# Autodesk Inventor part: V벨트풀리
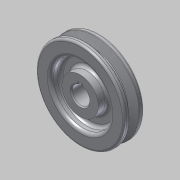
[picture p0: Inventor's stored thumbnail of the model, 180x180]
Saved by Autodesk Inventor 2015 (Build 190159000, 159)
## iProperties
Created: 2018-11
Part Number: V벨트풀리
Material: 알루미늄 6061
Document SubType Name: Modeling
Designer: mduedu
Density: 1 g/cm^3
Appearance: 알루미늄 - 평지
Author: mduedu
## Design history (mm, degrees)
sketch "스케치1"
  geometry: L1 (-9.5, 0)-(9.5, 0); L2 (9.5, 0)-(9.5, 42.7); L3 (9.5, 42.7)-(-9.5, 42.7); L4 (-9.5, 42.7)-(-9.5, 0); L5 (-4.877, 42.7)-(-1.953, 33.7); L6 (-1.953, 33.7)-(1.953, 33.7); L7 (1.953, 33.7)-(4.877, 42.7); L8 (0, 0)-(0, 42.7); L9 (-9.5, 40)-(9.5, 40); 3 further points
  constraints: 18 end point, 8 point on line, 3 perpendicular, 2 midpoint, 2 parallel, 1 coincident, 1 horizontal, 1 other
  dimensions: "d0" = 85.4 diameter of L3 L1; "d2" = 19 distance of L2.end L3.end; "d3" = 80 diameter of L9 L1; "d4" = 36 deg angle of L7 L5; "d5" = 6.3 distance between parallel lines of L6 L9; "d6" = 8 distance of point (4, 40) point (-4, 40)
revolve "회전1" sketch "스케치1" stored, may be unused: angle "d7" = 90 deg
sketch "스케치2"
  geometry: L1 (-2.5, 8.124)-(2.5, 8.124); L2 (2.5, 8.124)-(2.5, 10.8); L3 (2.5, 10.8)-(-2.5, 10.8); L4 (-2.5, 10.8)-(-2.5, 8.124); A1 r 8.5 centre (0, 0) between (-2.5, 8.124) and (2.5, 8.124); 1 further point
  constraints: 8 end point, 2 parallel, 2 point on circle, 1 centre point, 1 coincident, 1 horizontal, 1 perpendicular
  dimensions: "d8" = 17 diameter of A1; "d10" = 19.3 dimension on A1 L3; "d11" = 5 distance of L2.end L3.end
extrude "돌출1" cut sketch "스케치2" stored distance "d12" = 10; taper "d13" = 0 deg
chamfer "모따기1" distance "d14" = 1; stored, may be unused: second distance "d15" = 2, angle "d16" = 45 deg
fillet "모깎기1" dims "d17" = 1, "d18" = 0.5, "d19" = 2
sketch "스케치3"
  geometry: C1 r 17.5 at (0, 0); C2 r 28.5 at (0, 0); 1 further point
  constraints: 2 centre point, 2 coincident
  dimensions: "d20" = 35 diameter of C1; "d23" = 57 diameter of C2
extrude "돌출2" cut sketch "스케치3" distance "d24" = 9.5; taper "d25" = 0 deg
fillet "모깎기2" dims "d26" = 3
node "솔리드1"
